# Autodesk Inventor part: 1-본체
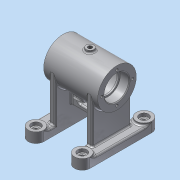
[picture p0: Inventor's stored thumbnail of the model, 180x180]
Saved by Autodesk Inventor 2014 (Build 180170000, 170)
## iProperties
Created: 2015-11
Part Number: 1-본체
Material: 알루미늄 6061
Document SubType Name: Modeling
Designer: 103-21
Mass: 358.521 g
Surface Area: 458.965 cm^2
Volume: 132.296 cm^3
Density: 2.71 g/cm^3
Appearance: 알루미늄 - 평지
Author: 103-21
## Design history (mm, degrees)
sketch "스케치1"
  geometry: L1 (40, -40)-(-40, -40); L2 (-40, -40)-(-40, 40); L3 (-40, 40)-(40, 40); L4 (40, 40)-(40, -40); L5 (40, -40)-(-40, 40); L6 (-40, -40)-(40, 40); L7 (-20, 40)-(-20, -40); L8 (20, 40)-(20, -40); 1 further point
  constraints: 16 end point, 4 point on line, 3 perpendicular, 2 midpoint, 2 parallel, 1 horizontal
  dimensions: "d0" = 20 distance of L7.start L2.end; "d1" = 20 distance of L3.end L8.start; "d2" = 80 distance of L1.end L2.end; "d3" = 80 distance between parallel lines of L4 L2
extrude "돌출1" new body sketch "스케치1" distance "d4" = 10; taper "d5" = 0 deg
sketch "스케치2"
  geometry: L1 (20, 40)-(40, 40) reference; L2 (40, -40)-(20, -40) reference; L3 (-40, -40)-(-40, 40) reference; L4 (-20, -40)-(-40, -40) reference; L5 (-20, 40)-(-20, -40) reference; L6 (-40, 40)-(-20, 40) reference; C1 r 10 at (30, 40); C2 r 10 at (-30, 40); C3 r 10 at (-30, -40); C4 r 10 at (30, -40); 1 further point
  constraints: 4 centre point, 4 midpoint, 3 equal radius
  dimensions: "d6" = 20 diameter of C3
extrude "돌출2" join sketch "스케치2" distance "d7" = 13; taper "d8" = 0 deg
node "작업 평면2"
sketch "스케치4"
  geometry: L1 (-35, 68)-(35, 68); L2 (-35, 84)-(-35, 93); L3 (-35, 93)-(35, 93); L4 (35, 93)-(35, 84); L5 (35, 84)-(23, 84); L6 (23, 84)-(23, 82); L7 (23, 82)-(21, 82); L8 (21, 82)-(21, 89); L9 (21, 89)-(-21, 89); L10 (-21, 89)-(-21, 82); L11 (-21, 82)-(-23, 82); L12 (-23, 82)-(-23, 84); L13 (-23, 84)-(-35, 84); L14 (-35, 84)-(-35, 68); L15 (35, 84)-(35, 68); 2 further points
  constraints: 30 end point, 10 parallel, 4 perpendicular, 2 point on line, 1 collinear, 1 horizontal, 1 midpoint, 1 vertical alignment
  dimensions: "d15" = 70 distance of L1.start L1.end; "d17" = 68 vertical distance of point (0, 0) L1.end; "d18" = 12 distance of L12.end L2.start; "d19" = 12 distance of L4.end L5.end; "d20" = 2 distance of L10.end L11.end; "d21" = 2 distance of L6.end L7.end; "d22" = 42 distance of L8.end L9.end (derived); "d23" = 28 diameter of L11 L1; "d24" = 32 diameter of L13 L1; "d25" = 42 diameter of L9 L1; "d26" = 32 diameter of L5 L1; "d27" = 50 diameter of L3 L1
revolve "회전1" stored, may be unused: angle "d28" = 90 deg
sketch "스케치5"
  geometry: L1 (0, 0)-(0, 80) reference; L2 (-68, 15)-(0, 15); L3 (-68, 65)-(0, 65); A1 r 25 centre (-68, 40) between (-68, 15) and (-68, 65) reference; 1 further point
  constraints: 4 end point, 2 perpendicular, 2 point on circle, 2 point on line, 2 tangent
extrude "돌출3" join sketch "스케치5" distance "d29" = 8; taper "d30" = 0 deg
node "작업 평면3"
node "작업 평면4"
sketch "스케치6"
  geometry: L1 (20, 68)-(28, 68) reference; L2 (28, 68)-(28, 68) reference; L3 (20, 68)-(28, 68) reference; L4 (20, 68)-(20, 68) reference; L5 (-28, 68)-(-20, 68) reference; L6 (-20, 68)-(-20, 68) reference; L7 (-28, 68)-(-20, 68) reference; L8 (-28, 68)-(-28, 68) reference; L9 (-35, 43)-(-35, 93) reference; L10 (35, 43)-(35, 93) reference; L11 (-28, 10)-(-20, 10) reference; L12 (-28, 68)-(-28, 10) reference; L13 (-28, 68)-(-20, 68) reference; L14 (-20, 10)-(-20, 68) reference; L15 (20, 10)-(28, 10) reference; L16 (20, 10)-(20, 68) reference; L17 (20, 68)-(28, 68) reference; L18 (28, 68)-(28, 10) reference; L19 (-35, 43)-(35, 43) reference; L20 (-20, 23)-(20, 23); L21 (-8, 36.5)-(8, 36.5); L22 (8, 29.5)-(-8, 29.5); L23 (40, 0)-(20, 0) reference; L24 (-20, 23)-(-20, 51.226); L25 (20, 51.226)-(20, 23); L26 (20, 51.226)-(-20, 51.226); A1 r 3.5 centre (8, 33) between (8, 29.5) and (8, 36.5); A2 r 3.5 centre (-8, 33) between (-8, 36.5) and (-8, 29.5); 2 further points
  constraints: 12 end point, 4 point on circle, 4 point on line, 4 tangent, 2 centre point, 2 parallel, 2 perpendicular, 1 collinear, 1 midpoint, 1 vertical alignment
  dimensions: "d32" = 20 distance between parallel lines of L20 L19; "d33" = 23 dimension on A1 A2; "d34" = 3.5 radius of A2; "d35" = 33 distance from line of A1.centre L23; "d36" = 28.22614 distance of L20.start L24.end
extrude "돌출4" join sketch "스케치6" stored distance "d37" = 8; taper "d38" = 0 deg
sketch "스케치7"
  geometry: C1 r 10 at (0, 0) reference; C2 r 10 at (0, 80) reference; C3 r 10 at (60, 80) reference; C4 r 10 at (60, 0) reference; 5 further points
  constraints: 4 coincident
hole "구멍1" sketch "스케치7" at (0, 80), (60, 80), (60, 0), (0, 0) diameter "d39" = 6; stored, may be unused: countersink angle "d43" = 82 deg, drill point angle "d45" = 118 deg; dims "d40" = 6, "d41" = 12, "d42" = 4, "d44" = 8
node "작업 평면5"
sketch "스케치8"
  geometry: C1 r 5 at (0, 0); 1 further point
  constraints: 1 centre point, 1 coincident
  dimensions: "d47" = 10 diameter of C1
extrude "돌출5" join sketch "스케치8" stored distance "d48" = 8; taper "d49" = 0 deg
node "작업 평면6"
sketch "스케치9"
  geometry: L1 (0, 0)-(-24.249, -14); L2 (-24.249, -14)-(0, 0); L3 (0, 0)-(-25, 0); 1 further point
  constraints: 6 end point, 1 collinear, 1 horizontal, 1 horizontal alignment, 1 other
  dimensions: "d50" = 28 distance of L1.end L1.start; "d51" = 30 deg angle of L1 L3
node "작업 평면7"
sketch "스케치10"
  geometry: L1 (8, -12.286)-(-8, -12.286) reference; L2 (-20, 21.651)-(-20, -7.349) reference; C1 r 6 at (0, 0); 1 further point
  constraints: 1 centre point
  dimensions: "d52" = 12 diameter of C1; "d54" = 20 distance from line of L2 C1.centre; "d55" = 12.2859 distance from line of L1 C1.centre
extrude "돌출6" join sketch "스케치10" stored distance "d56" = 8; taper "d57" = 0 deg
revolve "회전2" stored, may be unused: angle "d58" = 90 deg
node "작업 평면8"
sketch "스케치11"
  geometry: L1 (35, 25)-(-35, 25) reference; L2 (-35, 25)-(-35, -25) reference; 4 further points
  constraints: 2 midpoint, 1 horizontal alignment, 1 vertical alignment, 1 other
feature "엠보싱1" sketch "스케치11" dims "d59" = 0.5, "d60" = 0
sketch "스케치12"
  geometry: C1 r 16 at (0, 0) reference; C2 r 25 at (0, 0) reference; A1 r 20 centre (0, 0) between (20, 0) and (-20, 0); 3 further points
  constraints: 4 point on circle, 2 horizontal alignment, 2 vertical alignment, 1 centre point, 1 coincident
  dimensions: "d61" = 40 diameter of A1
hole "구멍2" sketch "스케치12" at (20, 0), (-20, 0), (0, -20), (0, 20) diameter "d62" = 3.242; stored, may be unused: countersink angle "d66" = 82 deg, drill point angle "d68" = 118 deg; dims "d63" = 8, "d64" = 12, "d65" = 4, "d67" = 10
node "작업 평면9"
sketch "스케치13"
  geometry: C1 r 5 at (0, 0) reference; 1 further point
  constraints: 1 coincident
hole "구멍3" sketch "스케치13" at (0, 0) diameter "d69" = 5.188; stored, may be unused: countersink angle "d73" = 82 deg, drill point angle "d75" = 0 deg; dims "d70" = 8, "d71" = 12, "d72" = 4, "d74" = 10
sketch "스케치14"
  geometry: C1 r 6 at (0, 0) reference; 2 further points
  constraints: 1 coincident
hole "구멍4" sketch "스케치14" at (0, 0) diameter "d76" = 5.188; stored, may be unused: countersink angle "d80" = 82 deg, drill point angle "d82" = 0 deg; dims "d77" = 8, "d78" = 12, "d79" = 4, "d81" = 10
fillet "모깎기1" dims "d83" = 3, "d84" = 0.3, "d85" = 2
fillet "모깎기3" dims "d88" = 2
fillet "모깎기4" dims "d89" = 2
fillet "모깎기5" dims "d90" = 2
fillet "모깎기6" dims "d91" = 2
fillet "모깎기7" dims "d92" = 2
chamfer "모따기1" distance "d93" = 1; stored, may be unused: second distance "d94" = 2, angle "d95" = 45 deg
node "솔리드1"
mirror "대칭1"
mirror "대칭2"
node "투영된 루프1"
node "투영된 루프2"
node "투영된 루프3"
node "투영된 루프4"
node "투영된 루프5"
node "투영된 루프6"
node "투영된 루프7"
node "투영된 루프8"
other parameters: "d14" = 0, "d31" = 0, "d46" = -96
